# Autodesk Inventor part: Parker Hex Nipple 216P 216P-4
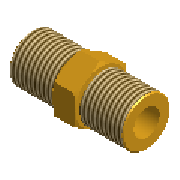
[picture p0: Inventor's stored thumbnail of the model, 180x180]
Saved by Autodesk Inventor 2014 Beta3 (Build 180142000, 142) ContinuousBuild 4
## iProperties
NAME: PIPING: Parker Hex Nipple 216P
DATA: <meta><inlinegroups number="1" deflen="2.4638"></inlinegroups><connections number="2"></connections><angles><a>3.14159265358979</a></angles></meta>
Created: 2010-12
Part Number: Parker Hex Nipple 216P 216P-4
Material: Brass, Soft Yellow
Description: Hex Nipple
Document SubType Name: Modeling
Standard: Parker
Designer: Beta-8540w
Manufacturer: Parker
Language: en-US
Size Designation: 216P-4
Categories: <MemberInstance><Categories><Category DisplayName="Tube &amp; Pipe" InternalName="4347fa0f-2144-441d-94cd-e3e15c92b736" Mnemonic="TUBEANDPIPE"><CategoryParamete
Density: 8.47 g/cm^3
Appearance: Brass - Satin
IsCustomPart: 0
Author: Beta-8540w
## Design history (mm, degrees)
sketch "Sketch1"
  geometry: L1 (8.249, 0)-(4.124, -7.144); L2 (4.124, -7.144)-(-4.124, -7.144); L3 (-4.124, -7.144)-(-8.249, 0); L4 (-8.249, 0)-(-4.124, 7.144); L5 (-4.124, 7.144)-(4.124, 7.144); L6 (4.124, 7.144)-(8.249, 0); 2 further points
  constraints: 12 end point, 1 coincident, 1 horizontal, 11 other
  dimensions: "d0" = 14.2875 distance between parallel lines of L5 L2 (= C_HEX)
extrude "Extrusion1" new body sketch "Sketch1" stored distance "d1" = 7.0104 (= 0.2 x L); taper "d2" = 0 deg
sketch "Sketch2"
  geometry: L1 (0, 0)-(7.075, 0); L2 (-3.505, 0)-(-17.526, 0); L3 (-3.505, 0)-(-3.505, 6.072); L4 (-3.505, 6.072)-(-4.206, 6.072); L5 (-4.206, 6.072)-(-4.206, 6.858); L6 (-4.206, 6.858)-(-17.526, 6.858); L7 (-17.526, 6.858)-(-17.526, 0); L8 (-22.446, 0)-(11.995, 0) reference; L9 (-3.505, 4.124)-(-3.505, -4.124) reference
  constraints: 14 end point, 3 parallel, 2 collinear, 2 perpendicular, 2 point on line
  dimensions: "d3" = 14.0208 distance of L2.start L2.end (= 0.4 x L); "d6" = 13.31976 distance from line of L4.end L7 (= 0.38 x L); "d32" = 13.716 diameter of L6 L1; "d33" = 12.14437 diameter of L4 L1 (= 0.85 x C_HEX)
revolve "Revolution1" sketch "Sketch2" stored, may be unused: angle "d7" = 90 deg
mirror "Mirror1"
sketch "Sketch5"
  geometry: L1 (3.505, -7.144)-(-3.505, -7.144) reference; L2 (-3.505, -7.144)-(-3.505, -14.287); L3 (-3.505, -7.144)-(-0.174, -14.287); L4 (-3.505, -14.287)-(-0.174, -14.287); L5 (0, -15.716)-(0, -5.715) reference; L6 (4.907, 0)-(-4.907, 0) reference
  constraints: 6 end point, 2 perpendicular
  dimensions: "d15" = 7.14375 distance of L1.end L2.end (= 0.5 x C_HEX); "d38" = 25 deg angle of L2 L3
revolve "Revolution4" sketch "Sketch5" stored, may be unused: angle "d16" = 90 deg
mirror "Mirror2"
chamfer "Chamfer1" distance "d17" = 0.28575 (= 0.02 x C_HEX); stored, may be unused: second distance "d18" = 3.175, angle "d19" = 45 deg
hole "Hole1" diameter "d22" = 7.9756 (= D); stored, may be unused: countersink angle "d26" = 82 deg, drill point angle "d28" = 118 deg; dims "d20" = 25.4, "d21" = 25.4, "d23" = 12.7, "d24" = 9.525, "d25" = 6.35, "d27" = 19.05
thread "Thread1" dims "d34" = 25.4, "d35" = 0
thread "Thread2" dims "d36" = 25.4, "d37" = 0
workaxis "Work Axis1"
workpoint "Work Point1"
workaxis "Work Axis2"
workpoint "Work Point2"
workaxis "Work Axis3"
workaxis "Work Axis4"
workpoint "Work Point3"
workpoint "Work Point4"
body "Solid1"
other parameters: "C_HEX" = 14.2875 [user parameter; used in 4 equation terms], "L" = 35.052 [user parameter; used in 3 equation terms], "D" = 7.9756 [user parameter; used in 1 equation term], "ND1" = 9.652 [user parameter], "Parker_No" = 12.345 [user parameter]
